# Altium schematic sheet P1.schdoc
size 297 x 209 mm; Symbol: Drawing-Symbol_A4; @Project Name: Starbie; @Page Count: 1; @Update Date: 2026-10-09; @Create Date: 2026-10-09; @Schematic Name: Schematic1; @Page No: 1; @Page Name: P1; Company: EasyEDA.com; Version: V1.0; Page Size: A4; Device: Drawing-Symbol_A4; @Create Time: 07:09:15; @Update Time: 07:09:15; Border: 1; Width: 1170; Height: 825; Region Start: 1; X Region Count: 6; Y Region Count: 4; Blade Width: 10; Title Block Position: 3; @Board Name: Board1
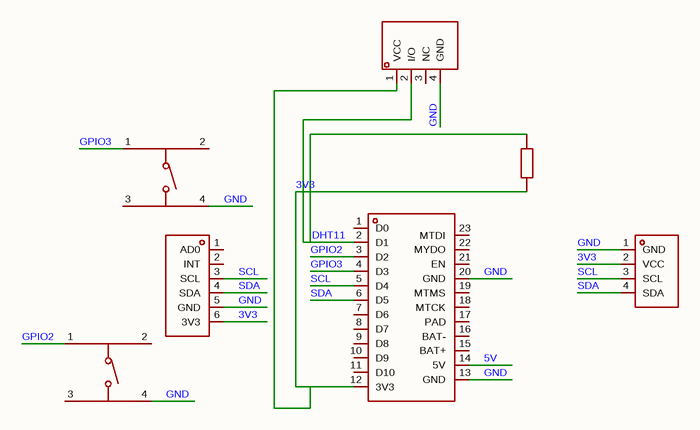
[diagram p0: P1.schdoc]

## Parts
KEY1  BUTTON1  [KEY-SMD_4P-L6.0-W6.0-P4.50-LS9.0]  (value not drawn)
KEY2  BUTTON1  [KEY-SMD_4P-L6.0-W6.0-P4.50-LS9.0]  (value not drawn)
OLED1  MC096GW  [OLED-TH_4P-L27.8-W27.3_MC096GW]  (value not drawn)
R1  10kΩ  [R1206]  (value not drawn)
S1  DHT11  [SENSOR-TH_DHT11-1]  (value not drawn)
U1  MPU6050-TH  [COMM-TH_MPU6050-TH]  (value not drawn)
U2  XIAO ESP32C3  [CONN-SMD_XIAO_ESP32C3]  (value not drawn)

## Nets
3V3: OLED1.2(VCC) R1.1 S1.1(VCC) U1.6(3V3) U2.12(3V3)
5V: U2.14(5V)
DHT11: R1.2 S1.2(I/O) U2.2(D1)
GND: KEY1.4 KEY2.4 OLED1.1(GND) S1.4(GND) U1.5(GND) U2.13(GND) U2.20(GND)
GPIO2: KEY2.1 U2.3(D2)
GPIO3: KEY1.1 U2.4(D3)
SCL: OLED1.3(SCL) U1.3(SCL) U2.5(D4)
SDA: OLED1.4(SDA) U1.4(SDA) U2.6(D5)

Not connected (* = marked no-connect by the designer): KEY1 2 3; KEY2 2 3; S1 3(NC); U1 1(AD0) 2(INT); U2 1(D0) 7(D6) 8(D7) 9(D8) 10(D9) 11(D10) 15(BAT+) 16(BAT-) 17(PAD) 18(MTCK) 19(MTMS) 21(EN) 22(MYDO) 23(MTDI)

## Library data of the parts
KEY1 KEY2 = BUTTON1: AddInBom: yes; ModelId: 6ea74a97f6274f24bd49b36d54f1829d0819f05c4eef4c71ace90d822a990e87; ModelName: KEY-SMD_4P-L6.0-W6.0-H5.0-LS10.0-P4.50; ModelTransform: 354.33,236.22,0,0,0,0,0,0,0
OLED1 = MC096GW: AddInBom: yes
R1 = 1206W4F1002T5E: Type:Thick Film Resistor Resistance:10kΩ Tolerance:±1% Tolerance:±1% Power(Watts):250mW Voltage-Supply(Max):200V Temperature Coefficient:±100ppm/℃ Temperature Coefficient:±100ppm/℃ Operating Temperature:-55℃~+155℃ Operating Temperature:-55℃~+155℃; Manufacturer: UNI-ROYAL(厚声); AddInBom: yes; ModelId: 04f48aacb8114155959811d2338bbb060819f05c4eef4c71ace90d822a990e87; ModelName: R1206_L3.2-W1.6-H0.6; ModelTransform: 125.984,62.992,0,0,0,0,0,0,0; Tolerance: ±1%; Power(Watts): 250mW; Voltage-Supply(Max): 200V
S1 = DHT11: Symbol: DHT11_C87032; AddInBom: yes; ModelId: 2faffe779d934ff5a302152923fcf6db0819f05c4eef4c71ace90d822a990e87; ModelTransform: 496.062,228.7397,0,0,0,0,0,-13.78,-196.85
U1 = MPU6050-TH: AddInBom: yes
U2 = XIAO ESP32C3: AddInBom: yes; ModelId: a507abe0117c42bdb14697a0ccadaebc0819f05c4eef4c71ace90d822a990e87; ModelName: CONN-SMD_113991054; ModelTransform: 699.9986,884.368,0,0,0,0,0,6.929,0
